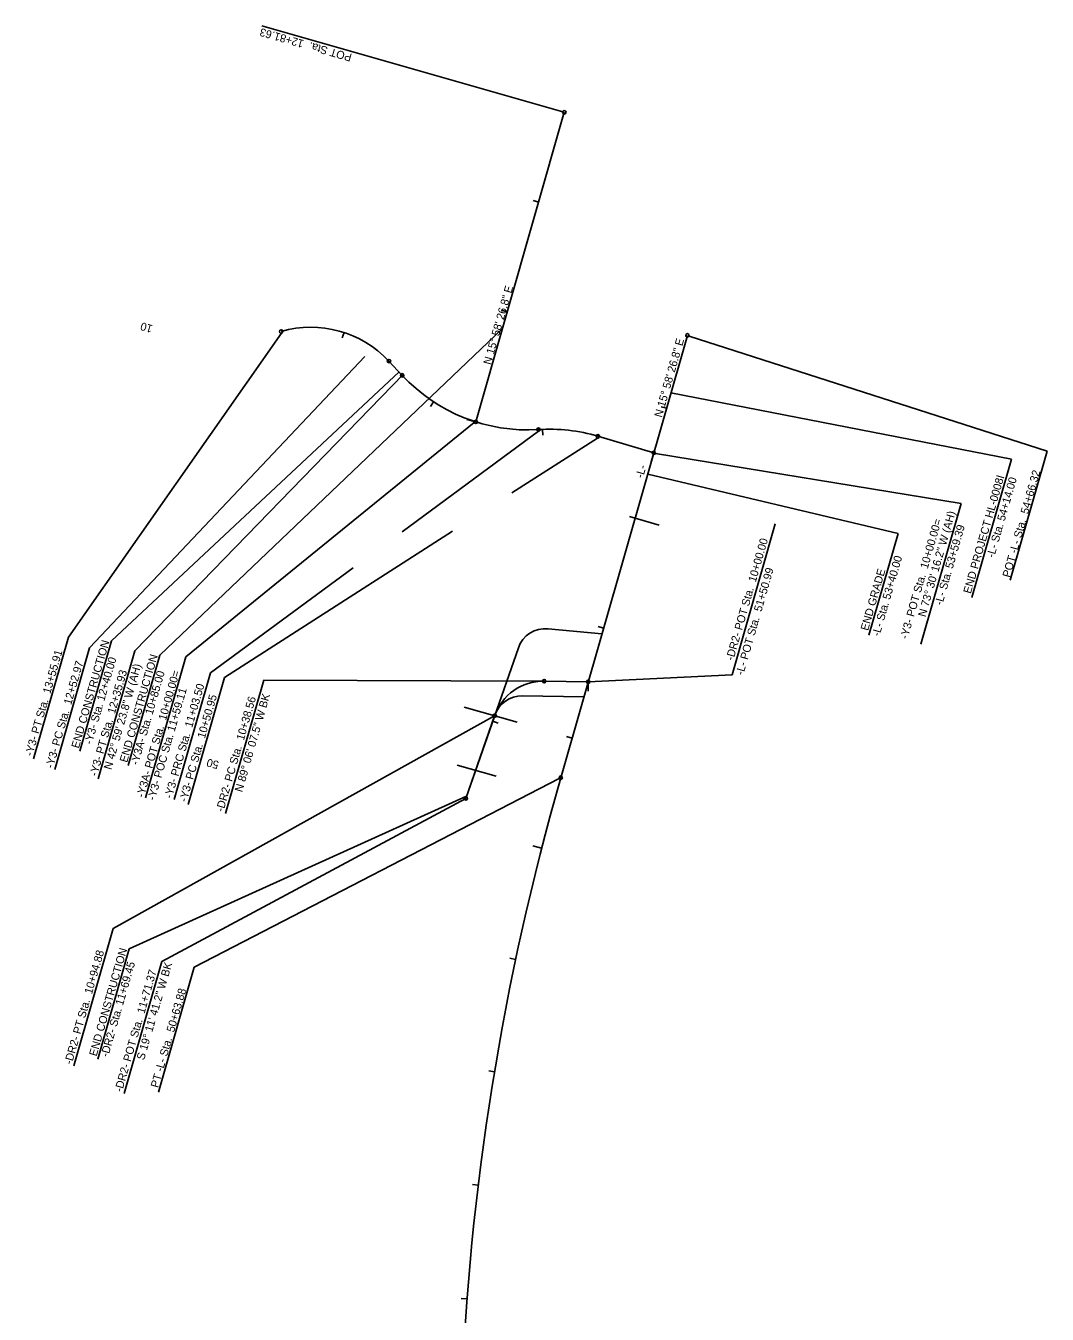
# Model space of a CAD drawing. Extents: x 2096901 to 2098386, y 684661 to 689731.
# Drawn here: x 2097405 to 2098298, y 688604 to 689731 of the extents above; entities that cross this region are included whole.
import ezdxf

# ---------------------------------------------------------------- set-up
doc = ezdxf.new("R2010")
doc.units = 0
for name, color, linetype in [('Prop Horizontal Alignment', 7, 'Continuous'), ('Prop Horizontal Alignment Direction Label', 7, 'Continuous'), ('Prop Horizontal Alignment Station Label', 7, 'Continuous'), ('Prop Horizontal Alignment Tick Label', 7, 'Continuous'), ('Prop Horizontal Alignment Tick Large', 7, 'Continuous'), ('Prop Horizontal Alignment Tick Small', 7, 'Continuous'), ('Scratch_Level_0', 7, 'Continuous'), ('Scratch_Level_2', 7, 'Continuous'), ('Scratch_Level_3', 7, 'Continuous'), ('Scratch_Level_5', 7, 'Continuous'), ('Scratch_Level_7', 7, 'Continuous'), ('Scratch_Level_8', 7, 'Continuous'), ('Scratch_Level_9', 7, 'Continuous')]:
    doc.layers.add(name, color=color, linetype=linetype)

msp = doc.modelspace()

# ---------------------------------------------------------------- linework, layer by layer
at = {"layer": 'Prop Horizontal Alignment'}
for p, q in [((2097798, 689384.4), (2097875.5, 689655.2)), ((2097872.4, 689073.2), (2097983.1, 689460.1)), ((2097733.8, 689425.1), (2097722.2, 689437.6)), ((2097953.7, 689357.3), (2097904.8, 689371.8)), ((2097896.3, 689157), (2097857.8, 689157.6)), ((2097814.6, 689127.4), (2097789.4, 689055.1))]:
    msp.add_line(p, q, dxfattribs=at)
for centre, radius, start, end in [((2097653.9, 689373.9), 93.3, 42.9899, 106.1927), ((2097843.5, 689527.4), 150, 222.9899, 273.5766), ((2097862.3, 689228), 150, 73.5045, 93.5766), ((2097857.1, 689112.6), 45, 89.1021, 160.8052), ((2100083.6, 688440.2), 2300, 164.0259, 177.8037)]:
    msp.add_arc(centre, radius, start, end, dxfattribs=at)
at = {"layer": 'Prop Horizontal Alignment Station Label'}
for p, q in [((2097874.1, 689655.6), (2097611.1, 689730.9)), ((2097628.3, 689462.1), (2097442.1, 689196.1)), ((2097821.4, 689466.2), (2097521.9, 689180.3)), ((2097984.5, 689459.5), (2098297.6, 689358.8)), ((2097701.2, 689441.7), (2097460.5, 689186.8)), ((2097479.7, 689192.8), (2097731, 689428.1)), ((2097734.9, 689426.1), (2097500.1, 689184.1)), ((2097968.7, 689409.8), (2098266.4, 689351.7)), ((2097796.6, 689383.8), (2097544.7, 689178.9)), ((2097853, 689376.2), (2097733.7, 689288.3)), ((2097904.4, 689370.3), (2097829.7, 689322.3)), ((2097955.1, 689356.9), (2098222.4, 689313.1)), ((2098265.3, 689245.9), (2098297.6, 689358.8)), ((2098231.8, 689230.8), (2098266.4, 689351.7)), ((2097948.4, 689338.7), (2098167.3, 689286.7)), ((2098187.1, 689189.9), (2098222.4, 689313.1)), ((2097777.8, 689288.9), (2097578.5, 689160.7)), ((2098022.2, 689163.3), (2098059.9, 689295.1)), ((2098141.8, 689197.8), (2098167.3, 689286.7)), ((2097690.9, 689256.8), (2097566.3, 689165)), ((2097411.6, 689089.6), (2097442.1, 689196.1)), ((2097430, 689080.3), (2097460.5, 689186.8)), ((2097452.1, 689096.3), (2097479.7, 689192.8)), ((2097468.1, 689072.3), (2097500.1, 689184.1)), ((2097494.3, 689083.9), (2097521.9, 689180.3)), ((2097509.3, 689055.6), (2097544.7, 689178.9)), ((2097534.5, 689054.1), (2097566.3, 689165)), ((2097546.8, 689049.8), (2097578.5, 689160.7)), ((2097579.4, 689041.9), (2097612.8, 689158.4)), ((2097857.8, 689157.6), (2097612.8, 689158.4)), ((2097896.3, 689157), (2098022.2, 689163.3)), ((2097814.6, 689127.4), (2097481.2, 688941.4)), ((2097871, 689072.5), (2097551.9, 688907.4)), ((2097790.1, 689056.9), (2097495.2, 688923.4)), ((2097523.7, 688912.5), (2097789.4, 689055.1)), ((2097446.7, 688821.1), (2097481.2, 688941.4)), ((2097467.6, 688827), (2097495.2, 688923.4)), ((2097490.6, 688797), (2097523.7, 688912.5)), ((2097520.6, 688798.2), (2097551.9, 688907.4))]:
    msp.add_line(p, q, dxfattribs=at)
for centre in [(2097875.5, 689655.2), (2097627.9, 689463.5), (2097983.1, 689460.1), (2097722.2, 689437.6), (2097733.8, 689425.1), (2097798, 689384.4), (2097852.9, 689377.7), (2097904.8, 689371.8), (2097953.7, 689357.3), (2097857.8, 689157.6), (2097896.3, 689157), (2097814.6, 689127.4), (2097872.4, 689073.2), (2097789.4, 689055.1)]:
    msp.add_circle(centre, 1.5, dxfattribs=at)
at = {"layer": 'Prop Horizontal Alignment Tick Large'}
for p, q in [((2097798, 689384.4), (2097790.3, 689386.6)), ((2097953.7, 689357.3), (2097951.4, 689349.6)), ((2097896.3, 689157), (2097896.2, 689149)), ((2097855.6, 689011.6), (2097847.9, 689013.5))]:
    msp.add_line(p, q, dxfattribs=at)
at = {"layer": 'Prop Horizontal Alignment Tick Small'}
for p, q in [((2097853.1, 689576.7), (2097848.3, 689578.1)), ((2097825.5, 689480.6), (2097820.7, 689482)), ((2097683, 689462.6), (2097681.4, 689457.9)), ((2097761.2, 689402), (2097758.5, 689397.8)), ((2097964.9, 689396.4), (2097960.1, 689397.7)), ((2097856.4, 689377.8), (2097856.6, 689372.8)), ((2097937.4, 689300.2), (2097932.5, 689301.6)), ((2097909.8, 689204.1), (2097905, 689205.5)), ((2097812.9, 689122.5), (2097817.6, 689120.9)), ((2097882.3, 689107.9), (2097877.5, 689109.3)), ((2097832.9, 688914.2), (2097828, 688915.2)), ((2097814.4, 688815.9), (2097809.5, 688816.7)), ((2097800.3, 688716.9), (2097795.3, 688717.5)), ((2097790.4, 688617.4), (2097785.4, 688617.8))]:
    msp.add_line(p, q, dxfattribs=at)
at = {"layer": 'Scratch_Level_0'}
for p, q in [((2097834.2, 689121.7), (2097787.8, 689135)), ((2097816, 689074.6), (2097781.9, 689084.1))]:
    msp.add_line(p, q, dxfattribs=at)
at = {"layer": 'Scratch_Level_2'}
msp.add_line((2097798, 689384.4), (2097875.5, 689655.2), dxfattribs=at)
at = {"layer": 'Scratch_Level_3'}
msp.add_line((2097872.4, 689073.2), (2097983.1, 689460.1), dxfattribs=at)
at = {"layer": 'Scratch_Level_5'}
for p, q in [((2097838.8, 689144.7), (2097892.6, 689143.9)), ((2097814.8, 689128), (2097789.4, 689055.1))]:
    msp.add_line(p, q, dxfattribs=at)
for centre, radius, start, end in [((2097838.4, 689119.7), 25, 89.1021, 160.8052), ((2100083.6, 688440.2), 2300, 164.0259, 177.8037)]:
    msp.add_arc(centre, radius, start, end, dxfattribs=at)
at = {"layer": 'Scratch_Level_7'}
for p, q in [((2097861.3, 689203.5), (2097908.4, 689199)), ((2097835.3, 689186.8), (2097789.4, 689055.1))]:
    msp.add_line(p, q, dxfattribs=at)
msp.add_arc((2097858.9, 689178.6), 25, 84.595, 160.8052, dxfattribs=at)
at = {"layer": 'Scratch_Level_8'}
for p, q in [((2097896.3, 689157), (2097857.8, 689157.6)), ((2097814.6, 689127.4), (2097789.4, 689055.1))]:
    msp.add_line(p, q, dxfattribs=at)
msp.add_arc((2097857.1, 689112.6), 45, 89.1021, 160.8052, dxfattribs=at)
at = {"layer": 'Scratch_Level_9'}
for p, q in [((2097733.8, 689425.1), (2097722.2, 689437.6)), ((2097953.7, 689357.3), (2097904.8, 689371.8)), ((2097937.4, 689300.2), (2097958.4, 689294.2))]:
    msp.add_line(p, q, dxfattribs=at)
for centre, radius, start, end in [((2097653.9, 689373.9), 93.3, 42.9899, 106.1927), ((2097843.5, 689527.4), 150, 222.9899, 273.5766), ((2097862.3, 689228), 150, 73.5045, 93.5766)]:
    msp.add_arc(centre, radius, start, end, dxfattribs=at)

# ---------------------------------------------------------------- texts
at = {"layer": 'Prop Horizontal Alignment Direction Label'}
for s, rotation, p in [('N 15%%d 58\' 26.8" E', 74.0259, (2097811.2, 689433.9)), ('N 15%%d 58\' 26.8" E', 74.0259, (2097960.7, 689387.8)), ('N 73%%d 30\' 16.2" W (AH)', 74.0259, (2098191.2, 689213.3)), ('N 42%%d 59\' 23.8" W (AH)', 74.0259, (2097479.4, 689079.7)), ('N 89%%d 06\' 07.5" W BK', 74.035, (2097593.9, 689060.1)), ('S 19%%d 11\' 41.2" W BK', 73.7737, (2097508.1, 688825.7))]:
    msp.add_text(s, height=7, rotation=rotation, dxfattribs=at).set_placement(p)
at = {"layer": 'Prop Horizontal Alignment Station Label'}
for s, rotation, p in [('POT Sta.  12+81.63', 164.0259, (2097690.3, 689706.1)), ('-L-', 74.0259, (2097944.2, 689334.7)), ('END PROJECT HL-0008I', 74.0259, (2098230.8, 689233.7)), ('-L- Sta. 54+14.00', 74.0259, (2098251.2, 689265.1)), ('POT -L- Sta.  54+66.32', 74.0259, (2098265, 689247.8)), ('-Y3- POT Sta.  10+00.00=', 74.0259, (2098175.5, 689193.9)), ('-L- Sta. 53+59.39', 74.0259, (2098205.8, 689223.5)), ('-DR2- POT Sta.  10+00.00', 74.0259, (2098023.2, 689175.2)), ('-L- Sta. 53+40.00', 74.0259, (2098151, 689196.4)), ('-L- POT Sta.  51+50.99', 74.0259, (2098031.9, 689162.4)), ('END GRADE', 74.0259, (2098141, 689201.3)), ('END CONSTRUCTION', 74.0259, (2097451.1, 689098.4)), ('-Y3- PT Sta.  13+55.91', 74.0259, (2097410.5, 689091.6)), ('-Y3- PC Sta.  12+52.97', 74.0259, (2097428.5, 689080.9)), ('-Y3- Sta. 12+40.00', 74.0259, (2097462.4, 689101.7)), ('END CONSTRUCTION', 74.0259, (2097493.3, 689086)), ('-Y3- PT Sta.  12+35.93', 74.0259, (2097467, 689074)), ('-Y3A- Sta. 10+85.00', 74.0259, (2097502.9, 689083.7)), ('-Y3A- POT Sta.  10+00.00=', 74.0259, (2097507.9, 689055.3)), ('-Y3- PRC Sta.  11+03.50', 74.0259, (2097532.4, 689054.5)), ('-Y3- POC Sta. 11+59.11', 74.0259, (2097517.6, 689052.9)), ('-Y3- PC Sta.  10+50.95', 74.0259, (2097545.3, 689051.5)), ('-DR2- PC Sta.  10+38.56', 74.0259, (2097577.4, 689042.8)), ('-DR2- PT Sta.  10+94.88', 74.0259, (2097444.9, 688821.9)), ('END CONSTRUCTION', 74.0259, (2097466.6, 688829.1)), ('-DR2- Sta. 11+69.45', 74.0259, (2097476.7, 688828.4)), ('-DR2- POT Sta.  11+71.37', 74.0259, (2097488.8, 688797.8)), ('PT -L- Sta.  50+63.88', 74.0259, (2097520.4, 688801.5))]:
    msp.add_text(s, height=7, rotation=rotation, dxfattribs=at).set_placement(p)
at = {"layer": 'Prop Horizontal Alignment Tick Label'}
for s, rotation, p in [('10', 164.0259, (2097516.2, 689468.8)), ('50', 165.6172, (2097574, 689087.4))]:
    msp.add_text(s, height=7, rotation=rotation, dxfattribs=at).set_placement(p)

doc.saveas('drawing.dxf')
